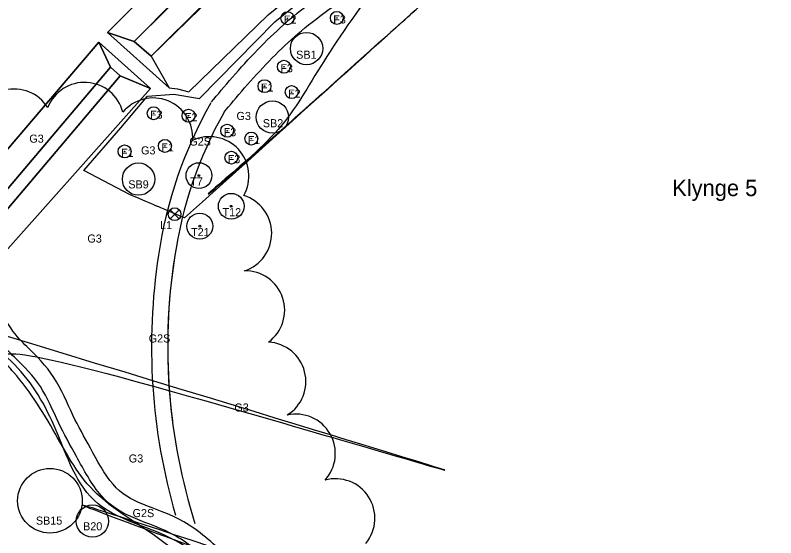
# Model space of a CAD drawing. Extents: x 0 to 512122, y 0 to 6212554.
# Drawn here: x 511501.5 to 511619.2, y 6211425.5 to 6211506.3 of the extents above; entities that cross this region are included whole.
import ezdxf

# ---------------------------------------------------------------- set-up
doc = ezdxf.new("R2010")
doc.units = 0
for name, color, linetype in [('_Låge L1', 7, 'Continuous'), ('_ny fruit trees', 7, 'Continuous'), ('_Paths', 7, 'Continuous'), ('_Spredmingskorridor', 7, 'Continuous'), ('_Spredmingskorridor_hatch', 7, 'Continuous'), ('Clouds', 7, 'Continuous'), ('L40 jord udlagt muld og grøft', 7, 'Continuous'), ('MatrikelnummerMaster', 7, 'Continuous'), ('Skel', 7, 'Continuous'), ('TV_U_AFM_Symbl_Gul', 7, 'Continuous'), ('TV_U_LYS_Ledn-ror', 7, 'Continuous'), ('TV_U_LYS_Mastenummer', 7, 'Continuous')]:
    doc.layers.add(name, color=color, linetype=linetype)

# ---------------------------------------------------------------- blocks, each defined once
blk = doc.blocks.new('SOLITAIRE TREES')
at = {"layer": 'Skel'}
for radius in [2, 0.141]:
    blk.add_circle((0, 0), radius, dxfattribs=at)

msp = doc.modelspace()

# ---------------------------------------------------------------- linework, layer by layer
at = {"layer": '_Låge L1'}
for p, q in [((511526.88, 6211476.21), (511525.48, 6211474.82)), ((511525.48, 6211476.21), (511526.88, 6211474.82))]:
    msp.add_line(p, q, dxfattribs=at)
msp.add_circle((511526.18, 6211475.52), 0.989, dxfattribs=at)
at = {"layer": '_ny fruit trees'}
for centre, radius in [((511543.64, 6211505.83), 1), ((511543.64, 6211505.83), 0.0426), ((511551.28, 6211505.87), 1), ((511551.28, 6211505.87), 0.0426), ((511543.1, 6211498.32), 1), ((511543.1, 6211498.32), 0.0426), ((511540.09, 6211495.32), 1), ((511540.09, 6211495.32), 0.0426), ((511544.29, 6211494.4), 1), ((511544.29, 6211494.4), 0.0426), ((511522.94, 6211491.14), 1), ((511528.33, 6211490.75), 1), ((511522.94, 6211491.14), 0.0426), ((511528.33, 6211490.75), 0.0426), ((511534.32, 6211488.43), 1), ((511534.32, 6211488.43), 0.0426), ((511538.05, 6211487.22), 1), ((511524.68, 6211486.08), 1), ((511538.05, 6211487.22), 0.0426), ((511518.45, 6211485.23), 1), ((511524.68, 6211486.08), 0.0426), ((511518.45, 6211485.23), 0.0426), ((511534.96, 6211484.26), 1), ((511534.96, 6211484.26), 0.0426)]:
    msp.add_circle(centre, radius, dxfattribs=at)
at = {"layer": '_Paths'}
msp.add_lwpolyline([(511526.16, 6211468.82), (511526.16, 6211468.81), (511526.16, 6211468.8)], dxfattribs=at)
for centre, radius, start, end in [((511590.71, 6211459.36), 67.73, 150.4856, 171.6628), ((511590.71, 6211459.36), 65.23, 150.6856, 171.6628), ((511615.72, 6211455.03), 93.11, 171.2575, 196.2313), ((511615.72, 6211455.03), 90.61, 171.2575, 187.2724), ((511615.72, 6211455.03), 90.61, 171.2575, 197.568)]:
    msp.add_arc(centre, radius, start, end, dxfattribs=at)
for points in [[(511533.83, 6211491.3), (511535.62, 6211493.43), (511540.82, 6211499.61), (511548.51, 6211506.42), (511560.79, 6211514.38), (511556.94, 6211518.3), (511552.05, 6211522.6)], [(511531.91, 6211492.91), (511533.7, 6211495.04), (511539.03, 6211501.36), (511546.99, 6211508.41), (511556.86, 6211514.81), (511555.22, 6211516.48), (511550.4, 6211520.72)], [(511614.91, 6211385.47), (511596.46, 6211390.92), (511585.44, 6211388.93), (511573.47, 6211390.64), (511563.45, 6211394.19), (511553.96, 6211398.16), (511541.55, 6211406.55), (511535.88, 6211415.76), (511532.61, 6211421.05), (511526.33, 6211426.35), (511519.92, 6211428.28), (511514.64, 6211431.24), (511510.82, 6211438.49), (511508.22, 6211443.01), (511505.66, 6211449.24), (511501.63, 6211453.21), (511498.11, 6211456.63), (511495.08, 6211463.57)], [(511619.19, 6211386.8), (511596.58, 6211393.48), (511585.39, 6211391.46), (511574.07, 6211393.08), (511564.35, 6211396.52), (511555.15, 6211400.37), (511543.4, 6211408.32), (511538, 6211417.07), (511534.53, 6211422.71), (511527.54, 6211428.6), (511520.9, 6211430.59), (511516.51, 6211433.06), (511513.01, 6211439.69), (511510.47, 6211444.11), (511507.78, 6211450.66), (511503.38, 6211454.99), (511500.2, 6211458.08), (511497.38, 6211464.57)]]:
    msp.add_open_spline(points, degree=3, dxfattribs=at)
at = {"layer": '_Spredmingskorridor'}
for points in [[(511618.63, 6211420.62), (511606.03, 6211410.57), (511596.93, 6211398.18), (511583.32, 6211390.02), (511570.81, 6211390.17), (511555.01, 6211396.48), (511539.8, 6211408.82), (511527.66, 6211423.86), (511513.19, 6211431.42), (511508.4, 6211440.66), (511501.75, 6211451.71), (511492.27, 6211459.06), (511618.63, 6211420.62), (511492.27, 6211459.06)], [(511446.92, 6211452.59), (511459.02, 6211449.61), (511483.05, 6211444.24), (511494.74, 6211426.25), (511518, 6211408.46), (511535.13, 6211387.3), (511545.81, 6211384.87), (511574.75, 6211382.07), (511593.15, 6211386.6), (511609.3, 6211398.19), (511446.92, 6211452.59), (511609.3, 6211398.19)]]:
    msp.add_open_spline(points, degree=3, dxfattribs=at)
at = {"layer": '_Spredmingskorridor_hatch'}
for points in [[(511581.75, 6211389.91), (511577.7, 6211389.37), (511567.86, 6211390.32), (511554, 6211396.47), (511538.61, 6211407.6), (511530.73, 6211425.91), (511512.75, 6211428.39), (511508.4, 6211441.83), (511502.76, 6211452.31), (511495.71, 6211456.96), (511492.31, 6211459.2)], [(511467.29, 6211448.87), (511473.27, 6211448.33), (511486.52, 6211446.7), (511493.23, 6211420.77), (511520.95, 6211413.24), (511528.73, 6211386.92), (511552.28, 6211384.43), (511571.21, 6211380.37), (511589.49, 6211384.41), (511596.58, 6211388.53), (511598.18, 6211389.58)]]:
    msp.add_open_spline(points, degree=3, dxfattribs=at)
at = {"layer": 'Clouds'}
for centre, start, end in [((511512.25, 6211489.81), 13.9833, 158.9833), ((511501.38, 6211488.77), 31.9594, 176.9594), ((511522.88, 6211487.4), 355.4261, 140.4261), ((511531.58, 6211481.41), 330.4679, 115.4679), ((511535.1, 6211472.57), 287.9805, 72.9805), ((511537.11, 6211460.67), 306.176, 91.176), ((511540.39, 6211449.65), 301.9704, 86.9704), ((511544.95, 6211438.52), 317.5852, 102.5852), ((511551.07, 6211428.52), 320.3783, 105.3783)]:
    msp.add_arc(centre, 6.1, start, end, dxfattribs=at)
at = {"layer": 'L40 jord udlagt muld og grøft'}
for points in [[(511519.91, 6211502.22), (511515.82, 6211503.61), (511525.25, 6211513.18), (511532.69, 6211519.82), (511545.02, 6211529.29), (511545.61, 6211524.88), (511539, 6211519.89), (511530.1, 6211512.31)], [(511519.91, 6211502.22), (511526.42, 6211508.85), (511529.16, 6211511.45), (511534.45, 6211516.15), (511539, 6211519.89), (511545.61, 6211524.88), (511547.65, 6211522.04), (511542.47, 6211518.17), (511533.87, 6211511), (511522.58, 6211499.95)], [(511525.32, 6211495.05), (511526.64, 6211494.9), (511528.4, 6211494.46), (511540.64, 6211506.35), (511547.4, 6211511.86), (511552.32, 6211515.55), (511551.86, 6211517.68), (511551.71, 6211519.73), (511547.63, 6211522.03), (511536.03, 6211512.89), (511531.05, 6211508.43), (511522.58, 6211499.95)], [(511515.82, 6211503.61), (511519.91, 6211502.22), (511522.58, 6211499.95), (511525.32, 6211495.05)], [(511489.13, 6211472.51), (511514.47, 6211502.13), (511516.25, 6211498.24), (511493.1, 6211470.93)], [(511522.45, 6211494.95), (511517.74, 6211496.9), (511516.25, 6211498.24), (511514.47, 6211502.13)], [(511516.25, 6211498.24), (511517.74, 6211496.9), (511494.5, 6211469.51), (511493.09, 6211470.93)], [(511517.74, 6211496.9), (511522.45, 6211494.94), (511496.13, 6211465.47), (511494.5, 6211469.51)]]:
    msp.add_lwpolyline(points, close=True, dxfattribs=at)
for points in [[(511519.91, 6211502.22), (511522.58, 6211499.95), (511533.87, 6211511), (511542.47, 6211518.17), (511547.65, 6211522.04), (511545.61, 6211524.88), (511539, 6211519.89), (511534.45, 6211516.15), (511529.16, 6211511.45), (511526.42, 6211508.85), (511519.91, 6211502.22), (511522.58, 6211499.95)], [(511515.82, 6211503.61), (511519.91, 6211502.22), (511522.58, 6211499.95), (511525.32, 6211495.05), (511515.82, 6211503.61)], [(511493.1, 6211470.93), (511516.25, 6211498.24), (511514.47, 6211502.13), (511489.13, 6211472.51), (511493.1, 6211470.93)], [(511514.47, 6211502.13), (511516.25, 6211498.24), (511517.74, 6211496.9), (511522.45, 6211494.95), (511514.47, 6211502.13)]]:
    msp.add_lwpolyline(points, dxfattribs=at)
at = {"layer": 'MatrikelnummerMaster'}
msp.add_lwpolyline([(511519.3, 6211478.52), (511512.13, 6211482.26), (511517.84, 6211488.88), (511521.98, 6211493.75), (511526.06, 6211494.09), (511530.02, 6211493.42), (511541.67, 6211505.27), (511553.25, 6211514.63), (511553.34, 6211518.92), (511555.87, 6211521.24), (511554.18, 6211524.58), (511556.19, 6211527.5), (511577, 6211538.18), (511581.94, 6211540.5), (511583.12, 6211540.67), (511588.16, 6211529.31)], dxfattribs=at)
for points in [[(511588.16, 6211529.31), (511582.04, 6211530.43), (511569.5, 6211526.54), (511558.5, 6211512.66), (511548.44, 6211498.44), (511543.23, 6211488.47), (511531.73, 6211479.28), (511527.73, 6211474.95), (511588.16, 6211529.31), (511527.73, 6211474.95)], [(511527.73, 6211474.95), (511519.3, 6211478.52), (511527.73, 6211474.95), (511519.3, 6211478.52)]]:
    msp.add_open_spline(points, degree=3, dxfattribs=at)
at = {"layer": 'TV_U_LYS_Mastenummer'}
for centre, radius in [((511546.59, 6211501.14), 2.5), ((511546.59, 6211501.14), 2.5), ((511541.31, 6211490.54), 2.5), ((511541.31, 6211490.54), 2.5), ((511520.6, 6211480.95), 2.5), ((511506.9, 6211431.21), 5), ((511513.47, 6211428.07), 2.5), ((511513.47, 6211428.07), 2.5)]:
    msp.add_circle(centre, radius, dxfattribs=at)

# ---------------------------------------------------------------- block references
at = {"layer": 'Skel'}
for p in [(511529.95, 6211481.49), (511534.95, 6211476.75), (511530.08, 6211473.68)]:
    msp.add_blockref('SOLITAIRE TREES', p, dxfattribs=at)

# ---------------------------------------------------------------- texts
at = {"layer": 'TV_U_AFM_Symbl_Gul'}
for s, p in [('F2', (511543.09, 6211504.99)), ('F3', (511550.73, 6211505.02)), ('SB1', (511544.99, 6211499.56)), ('F3', (511542.54, 6211497.47)), ('F1', (511539.54, 6211494.47)), ('F2', (511543.73, 6211493.55)), ('F3', (511522.38, 6211490.29)), ('F2', (511527.78, 6211489.9)), ('G3', (511535.76, 6211490.09)), ('SB2', (511539.83, 6211488.97)), ('F3', (511533.77, 6211487.58)), ('G3', (511503.71, 6211486.58)), ('G2S', (511528.46, 6211486.14)), ('F1', (511537.49, 6211486.37)), ('G3', (511520.99, 6211484.77)), ('F1', (511524.13, 6211485.23)), ('F1', (511517.9, 6211484.39)), ('F3', (511534.4, 6211483.41)), ('T7', (511528.6, 6211479.95)), ('SB9', (511519.02, 6211479.51)), ('T12', (511533.6, 6211475.21)), ('L1', (511523.93, 6211473.21)), ('T21', (511528.73, 6211472.14)), ('G3', (511512.69, 6211471.13)), ('G2S', (511522.18, 6211455.69)), ('G3', (511535.42, 6211445.01)), ('G3', (511519.1, 6211437.13)), ('G2S', (511519.68, 6211428.68)), ('SB15', (511504.72, 6211427.52)), ('B20', (511512.02, 6211426.64))]:
    msp.add_text(s, height=1.25, dxfattribs=at).set_placement(p)
at = {"layer": 'TV_U_LYS_Ledn-ror'}
msp.add_text('Klynge 5', height=2.53, dxfattribs=at).set_placement((511603.16, 6211478.32))

doc.saveas('drawing.dxf')
